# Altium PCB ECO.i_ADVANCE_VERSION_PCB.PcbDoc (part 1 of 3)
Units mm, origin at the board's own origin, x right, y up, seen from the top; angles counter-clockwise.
Board outline 291.08 x 101.6 mm, 4 copper layers (Top Layer, Layer 1, Layer 2, Bottom Layer), stack 1.161 mm thick; 272 components, 228 nets, 849 pads, 240 vias.
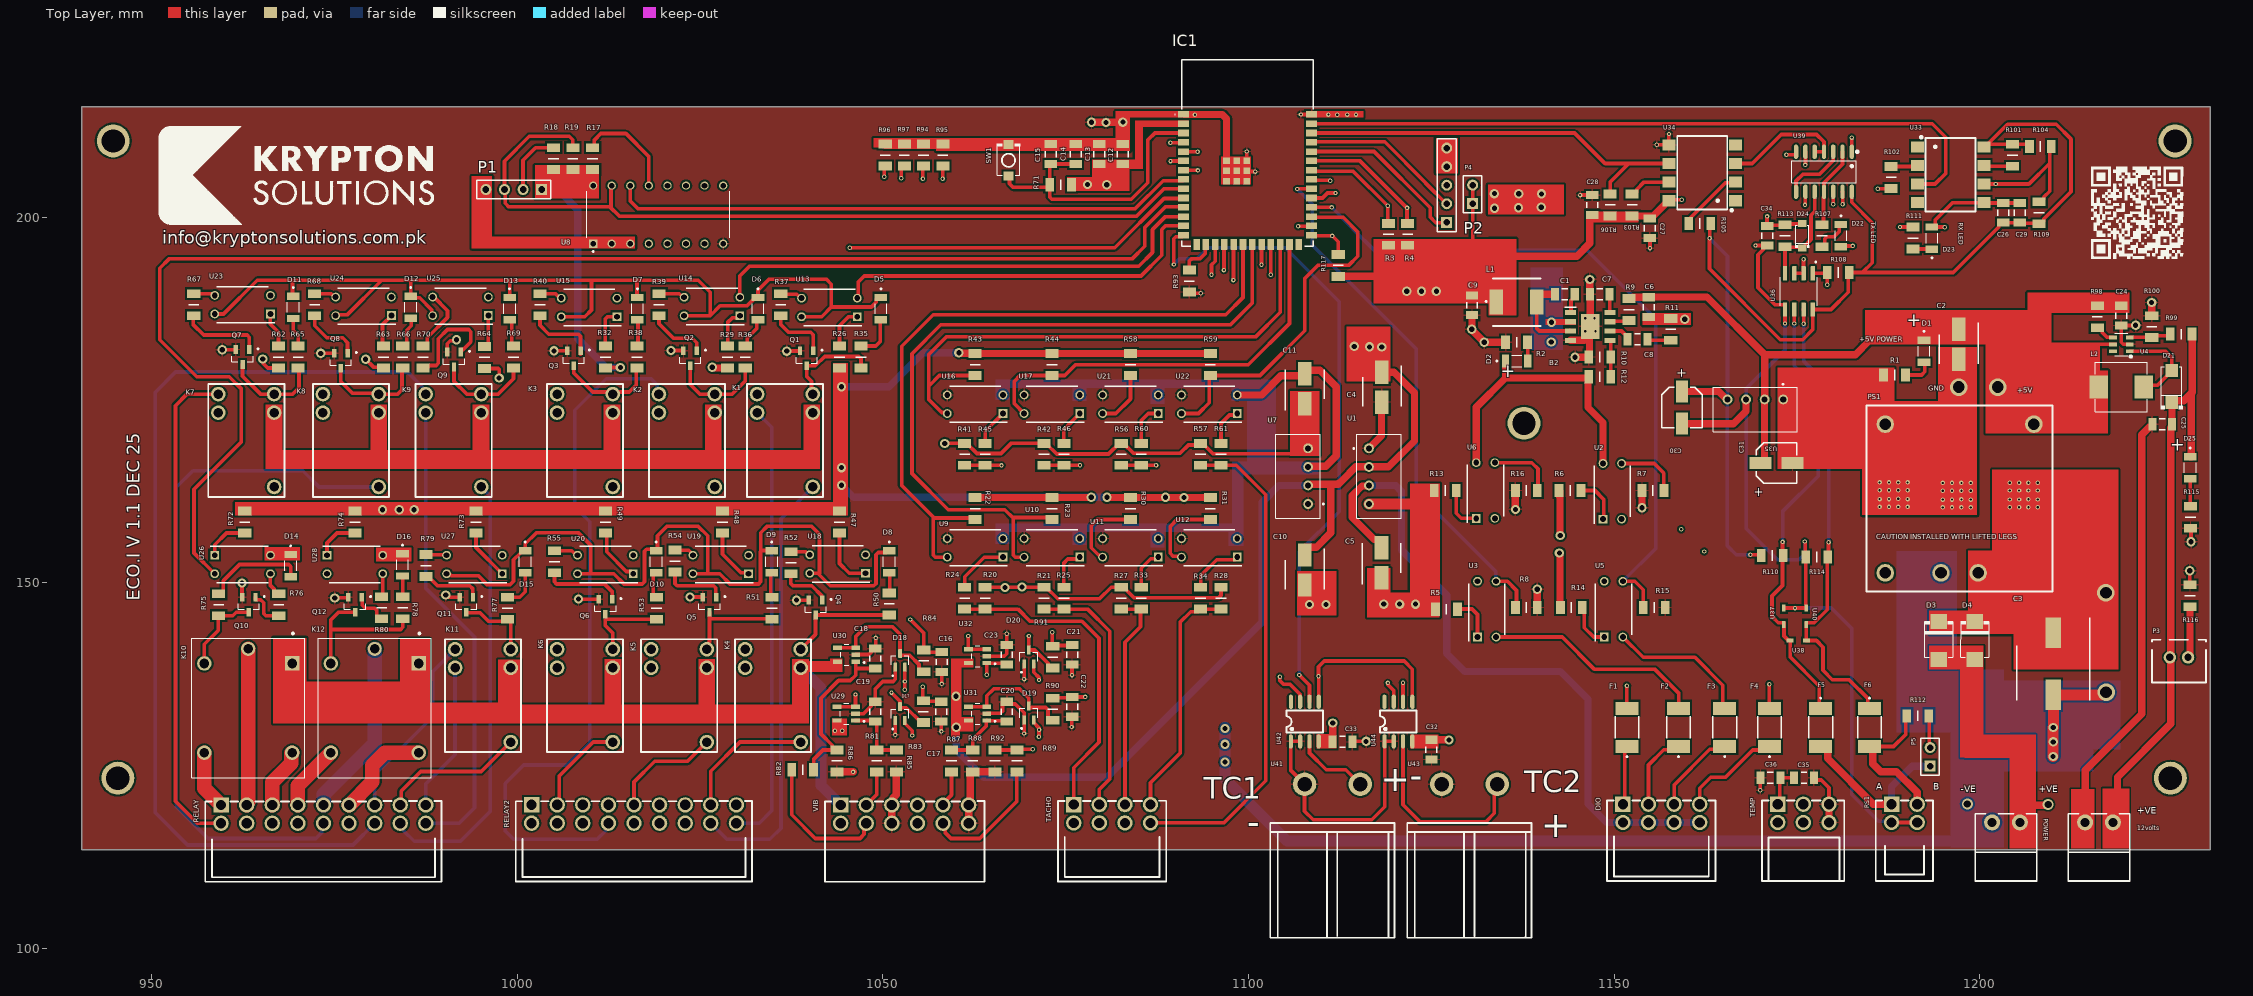
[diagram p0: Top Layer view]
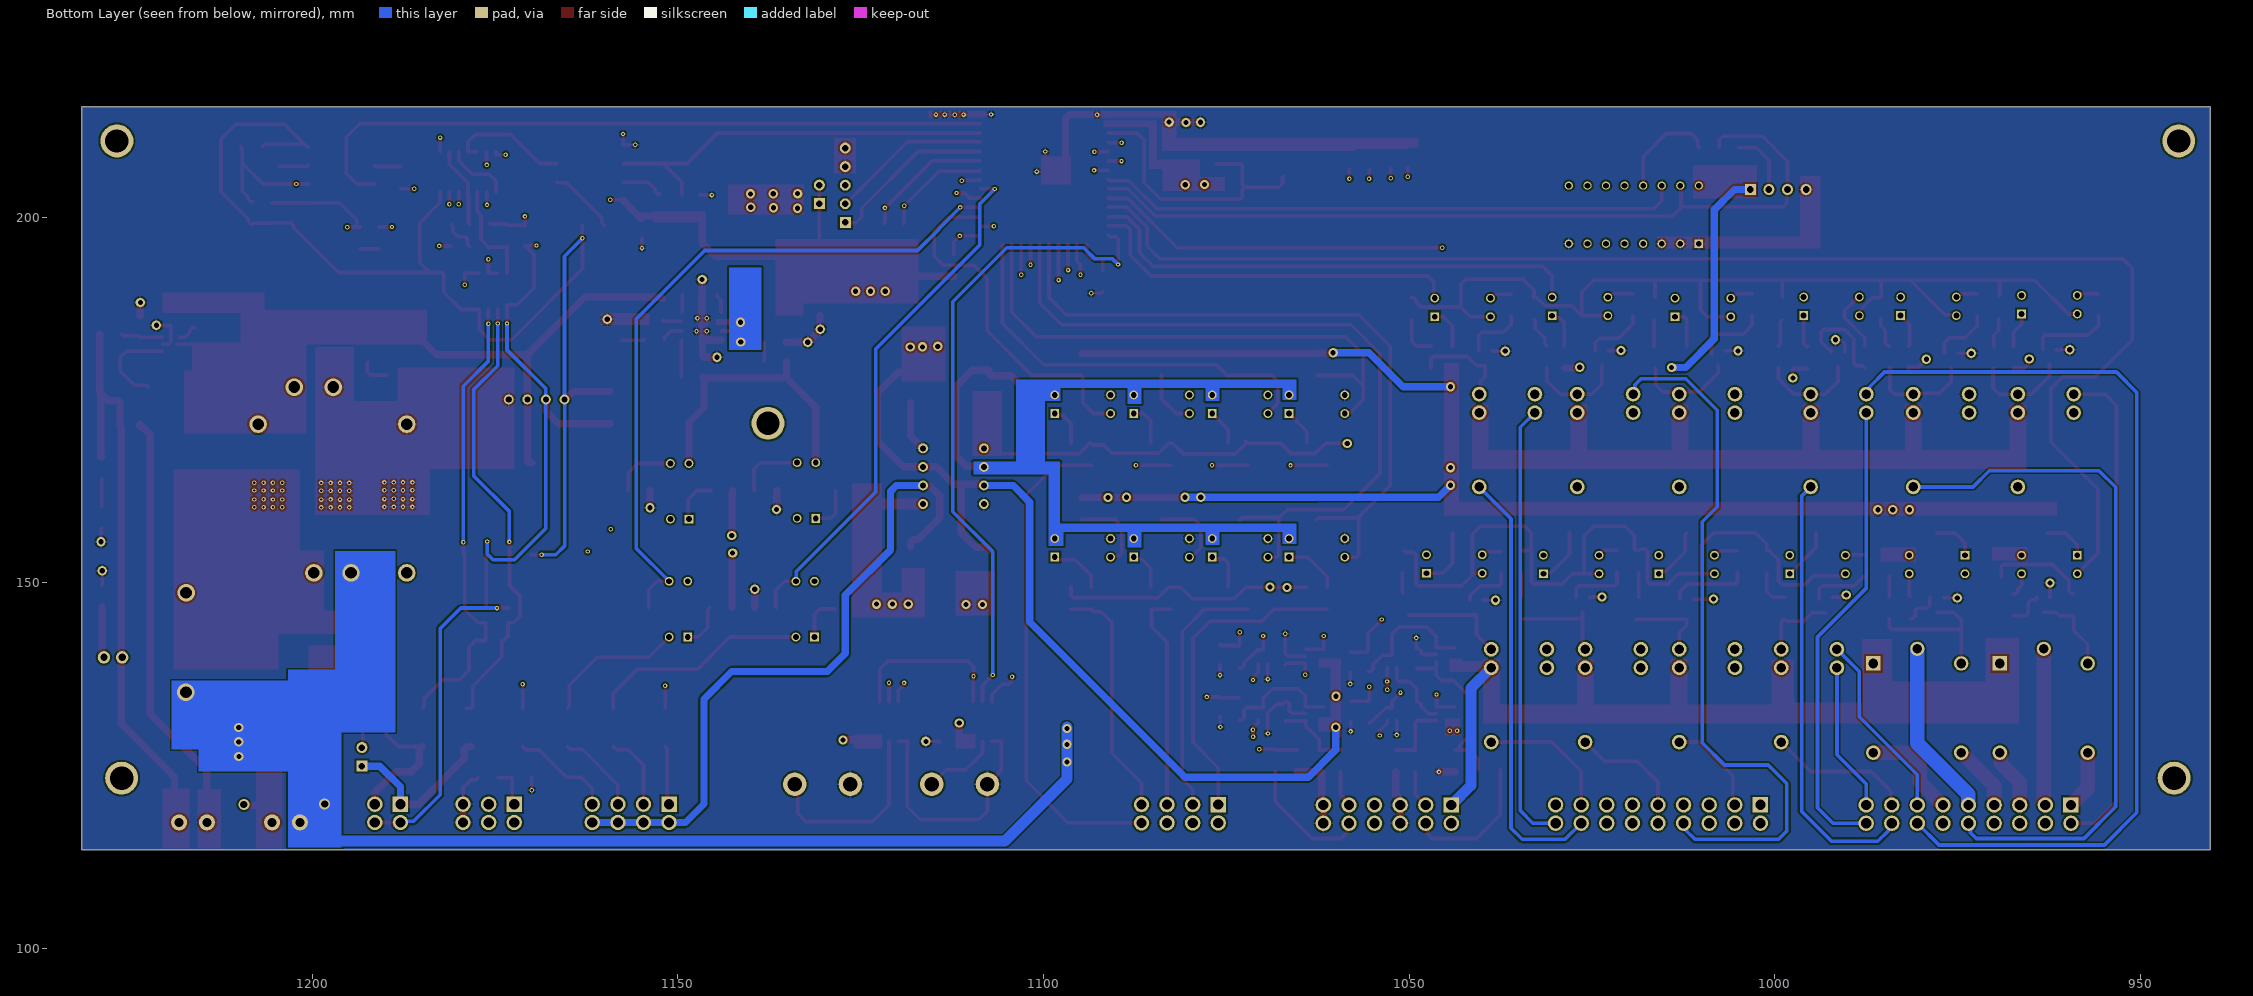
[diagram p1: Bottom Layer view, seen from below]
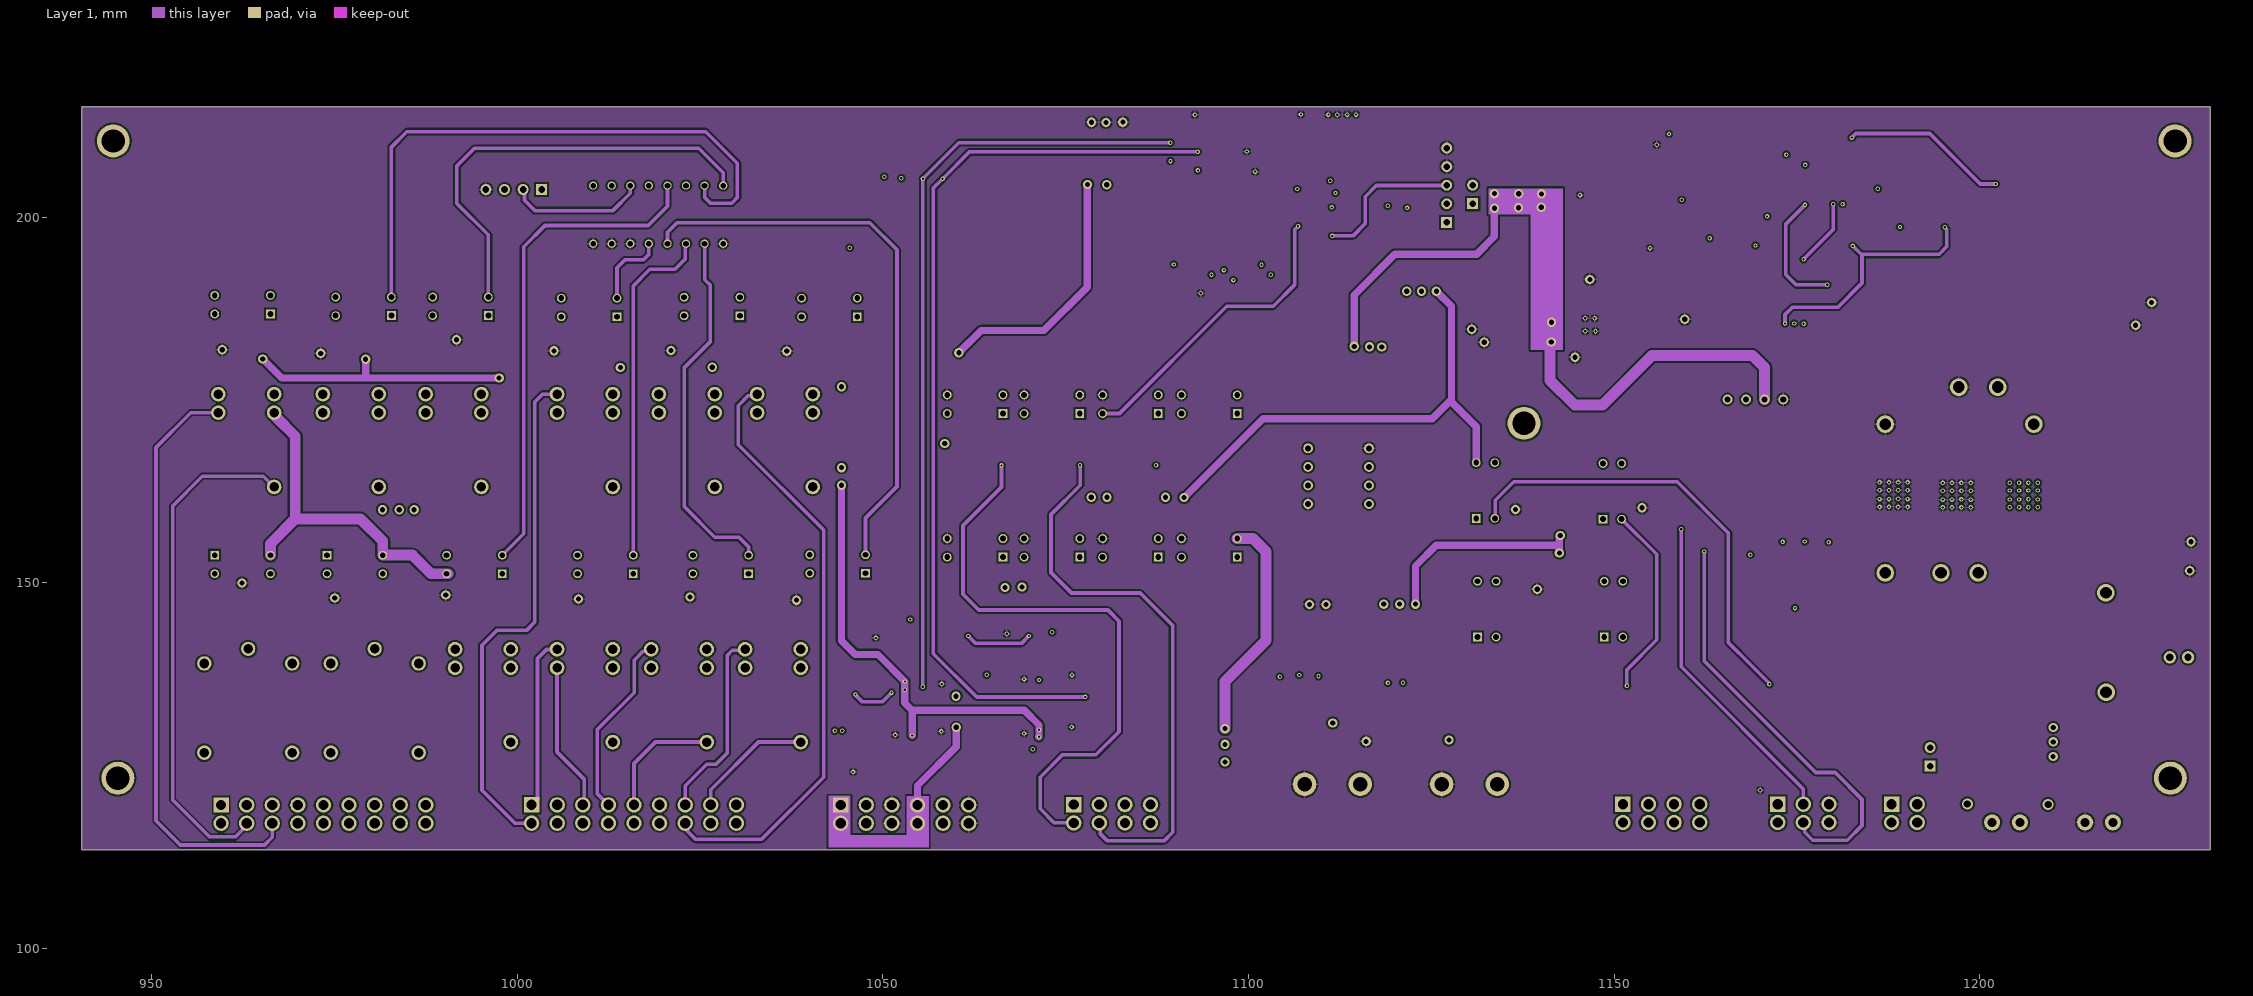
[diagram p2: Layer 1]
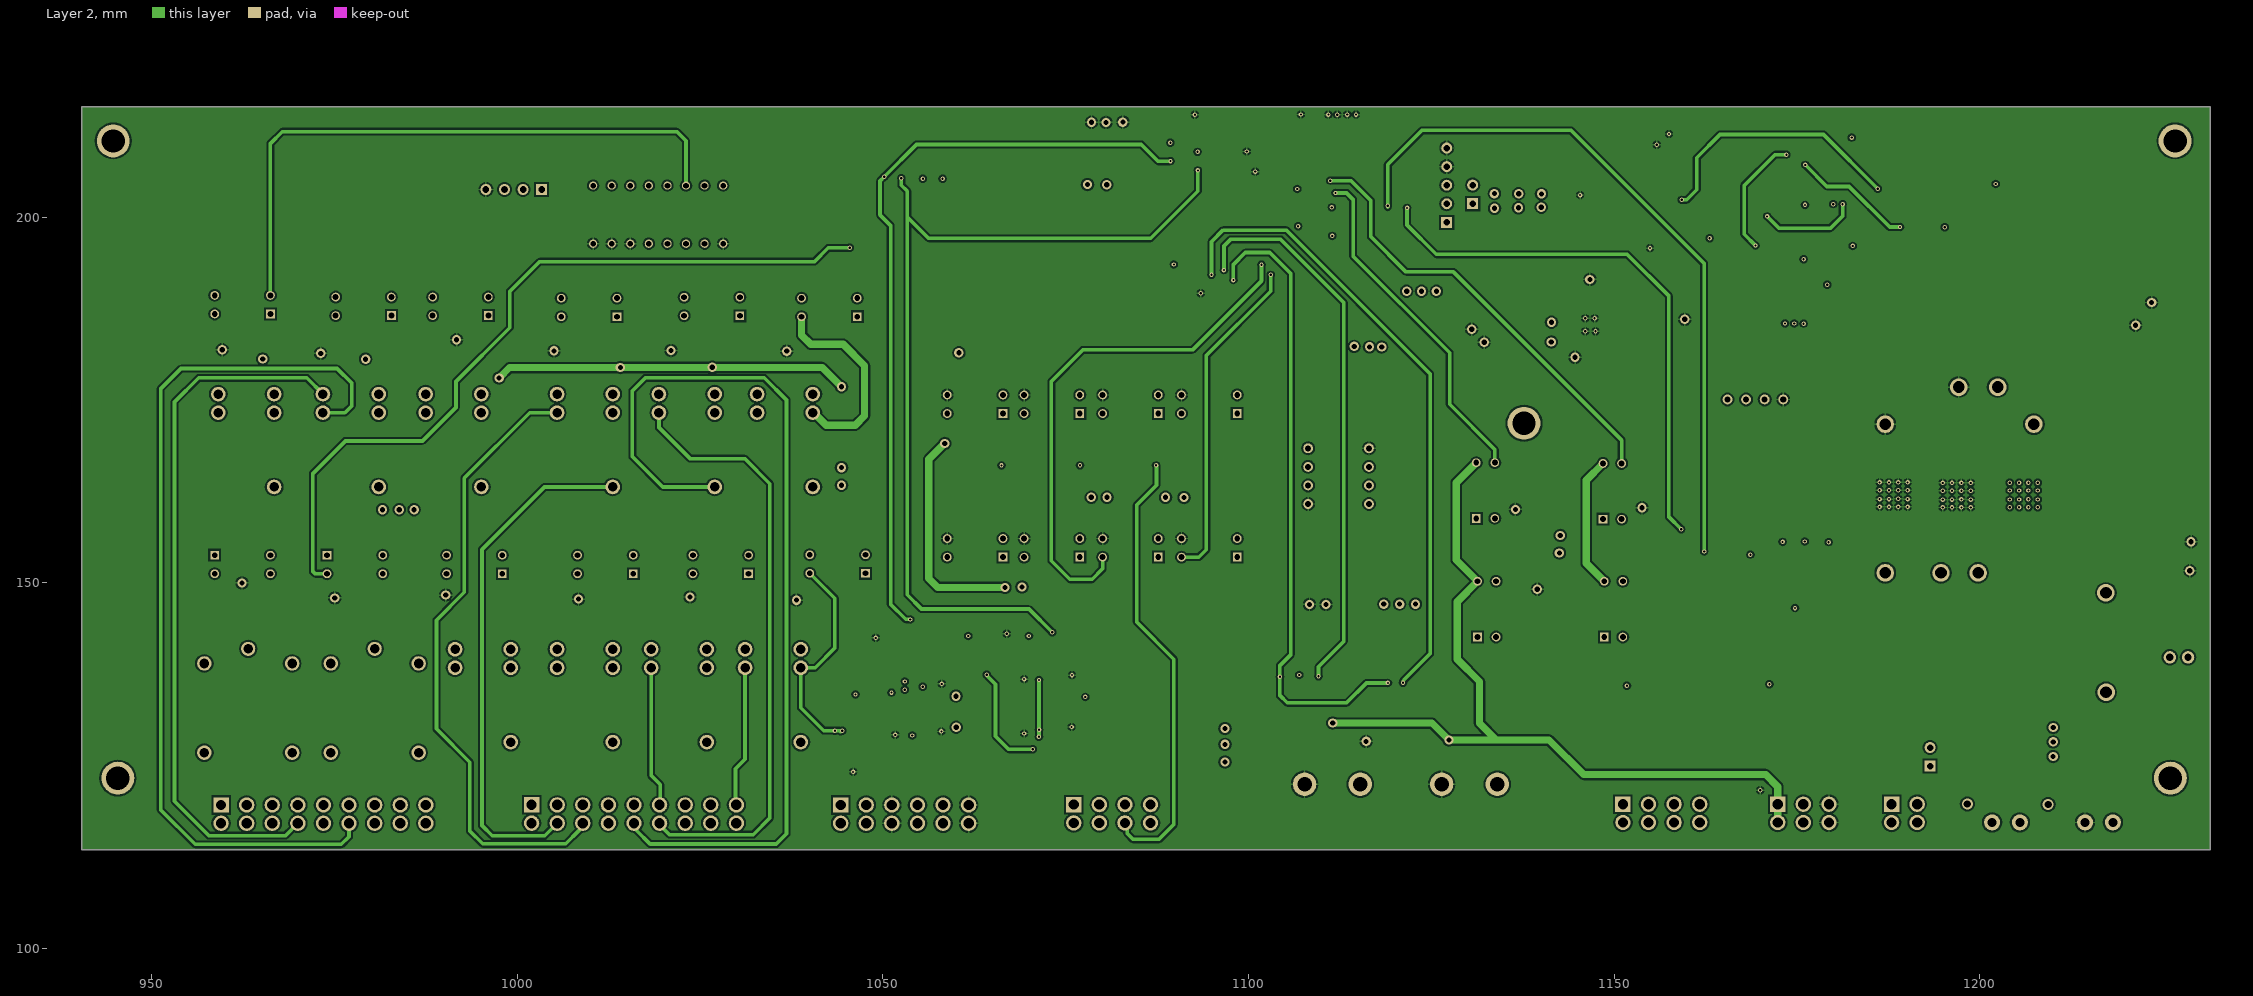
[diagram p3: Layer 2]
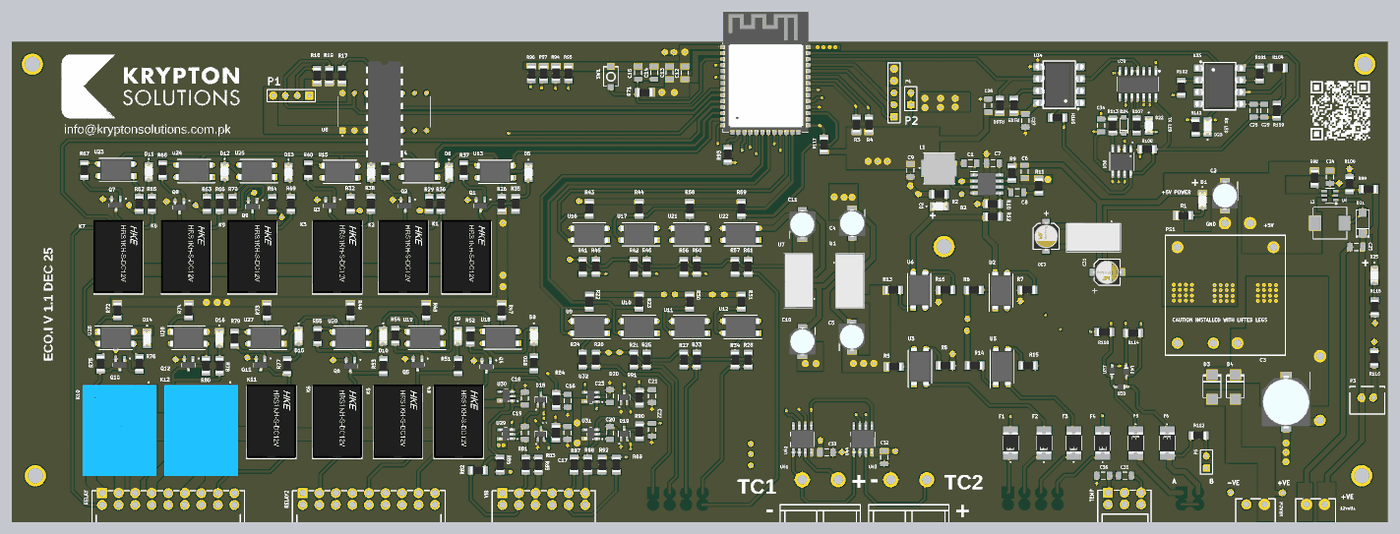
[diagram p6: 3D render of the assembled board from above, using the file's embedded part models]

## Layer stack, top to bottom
Top Solder: solder mask 0.0102, Solder Resist, Dk 3.5
Top Layer: signal copper 0.0356
Dielectric 2: prepreg 0.11, PP-006, Dk 4.1
Layer 1: signal copper 0.035
Dielectric 1: dielectric 0.8, FR-4, Dk 4.8
Layer 2: signal copper 0.035
Dielectric 3: prepreg 0.11, PP-006, Dk 4.1
Bottom Layer: signal copper 0.0356
Bottom Solder: solder mask 0.0102, Solder Resist, Dk 3.5

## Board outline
940.435,113.538 1231.519,113.538 1231.519,215.138 940.435,215.138

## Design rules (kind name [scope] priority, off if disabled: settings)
Clearance [All] p1: gap=0.254 ignorepadtopadclearanceinfootprint=TRUE except(0: Arc-Hole Track-Hole SMDPad-Hole THPad-Hole Via-Hole Fill-Hole Poly-Hole Region-Hole Text-Hole)
HoleSize [All] p1: absolutevalues=TRUE maxlimit=3.5 minlimit=0.025 maxpercent=80.000 minpercent=20.000
MinimumSolderMaskSliver [All] p1: minsoldermaskwidth=0.15
PolygonConnect [All] p1: connectstyle=Relief reliefconductorwidth=0.254 reliefentries=4 polygonreliefangle="90 Angle" airgapwidth=0.254
RoutingVias [All] p1: holewidth=0.72 width=1.27 viastyle="Through Hole" minholewidth=0.29 minwidth=0.5 maxholewidth=3.6 maxwidth=1.27
SilkToSolderMaskClearance [IsPad] p1: minsilkscreentomaskgap=0.01 clearancetoexposedcopper=TRUE
SolderMaskExpansion [All] p1: expansion=0.102 istentingtop=FALSE
SupplyNets "Schematic Supply Nets_10" [InNet('GND')] p1: voltage=0.000
SupplyNets "Schematic Supply Nets_9" [InNet('DGND')] p2: voltage=0.000
SupplyNets "Schematic Supply Nets_8" [InNet('+5V')] p3: voltage=0.000
SupplyNets "Schematic Supply Nets_7" [InNet('+48V')] p4: voltage=0.000
SupplyNets "Schematic Supply Nets_6" [InNet('+5_RS')] p5: voltage=0.000
SupplyNets "Schematic Supply Nets_5" [InNet('AGND')] p6: voltage=0.000
SupplyNets "Schematic Supply Nets_4" [InNet('FGND')] p7: voltage=0.000
SupplyNets "Schematic Supply Nets_3" [InNet('+5V_DIO')] p8: voltage=0.000
SupplyNets "Schematic Supply Nets_2" [InNet('+12')] p9: voltage=0.000
SupplyNets "Schematic Supply Nets_1" [InNet('+5V_FAN')] p10: voltage=0.000
SupplyNets "Schematic Supply Nets" [InNet('+3.3V')] p11: voltage=0.000
Width [All] p1: maxlimit=2 minlimit=0.254 preferedwidth=0.5 midlayer1_maxwidth=1.5 midlayer2_maxwidth=1.5 minimp=50.000000 maximp=50.000000 favimp=50.000000
27 further rules are at their usual default settings.

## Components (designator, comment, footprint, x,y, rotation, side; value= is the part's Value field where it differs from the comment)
12volts "DB2ERC-3.81-2P-BK" CONN-TH_2P-P3.81_DB2ERC-3.81-2P-BK 1216.291,117.247 r0 top
B2 "MP1484EN-LF-Z" SOIC127P600X170-9N 1146.73,185.079 r0 top
C1 "10nF" C1206 1143.252,189.465 r180 top
C2 "10uF" CAP-SMD_BD4.0-L4.3-W4.3-FD 1197.102,182.626 r270 top
C3 "47uF" CAPAE1000X1130N 1210.056,138.938 r270 top
C4 "10uF" CAP-SMD_BD4.0-L4.3-W4.3-FD 1118.235,176.784 r270 top
C5 "10uF" CAP-SMD_BD4.0-L4.3-W4.3-FD 1118.181,152.745 r90 top
C6 "4.7uF" C1206 1154.714,187.716 r270 top
C7 "100nF" C1206 1148.024,189.465 r180 top
C8 "6.8nF" C1206 1153.18,183.304 r0 top
C9 "10uF" C1206 1130.554,187.96 r90 top
C10 "10uF" CAP-SMD_BD4.0-L4.3-W4.3-FD 1107.694,151.765 r270 top
C11 "10uF" CAP-SMD_BD4.0-L4.3-W4.3-FD 1107.694,176.53 r90 top
C12 "22uF" C1206 1082.819,208.641 r90 top
C13 "100nF" C1206 1079.58,208.641 r90 top
C14 "100nF" C1206 1076.342,208.641 r90 top
C15 "100nF" C1206 1072.933,208.641 r90 top
C16 "100nF" C1206 1058.051,139.194 r270 top
C17 "100nF" C1206 1057.985,132.405 r270 top
C18 "100nF" C1206 1048.975,139.67 r90 top
C19 "100nF" C1206 1048.975,132.405 r90 top
C20 "100nF" C1206 1066.953,132.405 r90 top
C21 "100nF" C1206 1075.864,140.178 r270 top
C22 "100nF" C1206 1075.864,133.055 r270 top
C23 "100nF" C1206 1066.953,140.178 r90 top
C24 "22uF" C1206 1219.338,186.555 r270 top
C25 "22uF" C1206 1224.935,171.724 r180 top
C26 "100nF" C1206 1203.198,200.613 r90 top
C27 "100nF" C1206 1154.884,198.504 r270 top
C28 "100nF" C1206 1147.017,201.684 r90 top
C29 "100nF" C1206 1205.452,200.613 r90 top
C30 "10uF" WCAP-ASLI_D5H5.5 1159.277,173.982 r90 top
C31 "10uF" WCAP-ASLI_D5H5.5 1172.182,166.389 r180 top
C32 "100nF" C1206 1125.014,127.21 r90 top
C33 "100nF" C1206 1112.837,128.26 r180 top
C34 "100pF" C1206 1170.924,197.485 r90 top
C35 "100nF" C1206 1175.958,123.344 r0 top
C36 "100nF" C1206 1171.361,123.344 r180 top
D1 "LHN974_RED_LED_1206" LEDC3216X120N 1192.367,181.702 r270 top
D2 "LHN974_RED_LED_1206" LEDC3216X120N 1136.651,180.349 r0 top
D3 "RS3MB" diode_in 1189.94,140.529 r270 top
D4 "RS3MB" diode_in 1194.87,140.529 r270 top
D5 "LHN974_RED_LED_1206" LEDC3216X120N 1049.724,187.523 r270 top
D6 "LHN974_RED_LED_1206" LEDC3216X120N 1032.925,187.523 r270 top
D7 "LHN974_RED_LED_1206" LEDC3216X120N 1016.426,187.523 r270 top
D8 "LHN974_RED_LED_1206" LEDC3216X120N 1050.878,152.908 r270 top
D9 "LHN974_RED_LED_1206" LEDC3216X120N 1034.796,152.908 r270 top
D10 "LHN974_RED_LED_1206" LEDC3216X120N 1018.994,152.908 r270 top
D11 "LHN974_RED_LED_1206" LEDC3216X120N 969.377,187.673 r270 top
D12 "LHN974_RED_LED_1206" LEDC3216X120N 985.435,187.694 r270 top
D13 "LHN974_RED_LED_1206" LEDC3216X120N 998.962,187.523 r270 top
D14 "LHN974_RED_LED_1206" LEDC3216X120N 969.025,152.377 r270 top
D15 "LHN974_RED_LED_1206" LEDC3216X120N 1001.084,152.902 r270 top
D16 "LHN974_RED_LED_1206" LEDC3216X120N 984.312,152.462 r270 top
D17 "BAT54SWFILM" "SOT65P210X110-3N (BAT54SWFILM)" 1052.347,132.131 r90 top
D18 "BAT54SWFILM" "SOT65P210X110-3N (BAT54SWFILM)" 1052.347,139.414 r90 top
D19 "BAT54SWFILM" "SOT65P210X110-3N (BAT54SWFILM)" 1069.961,132.207 r90 top
D20 "BAT54SWFILM" "SOT65P210X110-3N (BAT54SWFILM)" 1069.961,139.89 r90 top
D21 "SS36" SMA_L4.4-W2.6-LS5.0-RD 1226.238,176.85 r90 top
D22 "LHN974_RED_LED_1206" LEDC3216X120N 1180.996,197.506 r270 top
D23 "LHN974_RED_LED_1206" LEDC3216X120N 1193.439,197.16 r90 top
D24 "1N4148W" SOD-123_L2.8-W1.8-LS3.7-RD-1 1175.725,197.485 r90 top
D25 "LHN974_RED_LED_1206" LEDC3216X120N 1228.762,165.742 r270 top
DIO "KF2EDGSR-3.5-2*4P" CONN-TH_8P-P3.50_KEFA_KF2EDGSR-3.5-2X4P 1154.571,103.659 r0 top
F1 "1812L200THPR" 1812L010DR 1151.737,130.243 r90 top
F2 "1812L200THPR" 1812L010DR 1158.806,130.243 r90 top
F3 "1812L200THPR" 1812L010DR 1165.112,130.243 r90 top
F4 "1812L200THPR" 1812L010DR 1171.22,130.243 r90 top
F5 "1812L200THPR" 1812L010DR 1178.237,130.243 r270 top
F6 "1812L200THPR" 1812L010DR 1184.89,130.243 r270 top
IC1 "ESP32-S3-WROOM-1-N16" ESP32S3WROOM1N16 1099.881,208.807 r0 top
K1 "HRS1KH-S-DC5V" RELAY-TH_HRS1KH-S-DCXXX 1041.808,161.6 r90 top
K2 "HRS1KH-S-DC5V" RELAY-TH_HRS1KH-S-DCXXX 1028.395,161.6 r90 top
K3 "HRS1KH-S-DC5V" RELAY-TH_HRS1KH-S-DCXXX 1014.454,161.6 r90 top
K4 "HRS1KH-S-DC5V" RELAY-TH_HRS1KH-S-DCXXX 1040.168,126.717 r90 top
K5 "HRS1KH-S-DC5V" RELAY-TH_HRS1KH-S-DCXXX 1027.326,126.717 r90 top
K6 "HRS1KH-S-DC5V" RELAY-TH_HRS1KH-S-DCXXX 1014.454,126.717 r90 top
K7 "HRS1KH-S-DC5V" RELAY-TH_HRS1KH-S-DCXXX 968.144,161.6 r90 top
K8 "HRS1KH-S-DC5V" RELAY-TH_HRS1KH-S-DCXXX 982.45,161.6 r90 top
K9 "HRS1KH-S-DC5V" RELAY-TH_HRS1KH-S-DCXXX 996.487,161.6 r90 top
K10 "SRD-05VDC-SL-C" RELAY_SRD-05VDC-SL-C 963.212,132.891 r270 top
K11 "HRS1KH-S-DC5V" RELAY-TH_HRS1KH-S-DCXXX 1000.51,126.717 r90 top
K12 "SRD-05VDC-SL-C" RELAY_SRD-05VDC-SL-C 980.51,132.891 r270 top
L1 "SRP6540-100M" SRP6540 1136.651,188.393 r0 top
L2 "22uH" IND-SMD_L7.3-W6.6_MHCI06030 1219.338,176.811 r180 top
P1 "OLED" HDR1X4 1003.336,203.802 r180 top
P2 "PROGRAMMING" HDR1X5 1126.972,209.468 r270 top
P3 "B2B-XH-A(LF)(SN)" CONN-TH_B2B-XH-A-LF-SN 1227.221,139.827 r180 top
P4 "Header 2" HDR1X2 1130.646,201.86 r90 top
P5 "Header 2" HDR1X2 1193.192,124.951 r90 top
POWER "DB2ERC-3.81-2P-BK" CONN-TH_2P-P3.81_DB2ERC-3.81-2P-BK 1203.571,117.247 r0 top
PS1 "URB4805YMD-10WR3" PS1 1188.587,140.529 r0 top
Q1 "FMMT493" SOT91P240X120-3N 1039.579,180.713 r180 top
Q2 "FMMT493" SOT91P240X120-3N 1023.644,180.713 r180 top
Q3 "FMMT493" SOT91P240X120-3N 1007.745,180.721 r180 top
Q4 "FMMT493" SOT91P240X120-3N 1040.803,146.637 r180 top
Q5 "FMMT493" SOT91P240X120-3N 1026.289,147.02 r180 top
Q6 "FMMT493" SOT91P240X120-3N 1012.056,146.748 r180 top
Q7 "FMMT493" SOT91P240X120-3N 962.438,180.892 r180 top
Q8 "FMMT493" SOT91P240X120-3N 975.877,180.407 r180 top
Q9 "FMMT493" SOT91P240X120-3N 991.351,180.554 r180 top
Q10 "FMMT493" SOT91P240X120-3N 963.292,147.02 r180 top
Q11 "FMMT493" SOT91P240X120-3N 993.034,147.02 r180 top
Q12 "FMMT493" SOT91P240X120-3N 977.823,147.02 r180 top
R1 "330Ω" RESC3216X75N 1188.339,178.435 r180 top
R2 "330Ω" RESC3216X75N 1136.651,182.918 r180 top
R3 "10kΩ" RESC3216X75N 1119.131,197.662 r270 top
R4 "4.7k" RESC3216X75N 1121.753,197.662 r270 top
R5 "330Ω" RESC3216X75N 1127.059,146.414 r180 top
R6 "330Ω" RESC3216X75N 1143.97,162.638 r180 top
R7 "10kΩ" RESC3216X75N 1155.293,162.638 r0 top
R8 "4.7k" RESC3216X75N 1137.99,146.643 r180 top
R9 "100kΩ" RESC3216X75N 1152.022,187.391 r270 top
R10 "10kΩ" RESC3216X75N 1148.024,180.888 r0 top
R11 "6.8k" RESC3216X75N 1157.737,184.679 r270 top
R12 "26.1kΩ" RESC3216X75N 1148.024,178.192 r180 top value=26.1k
R13 "330Ω" RESC3216X75N 1126.886,162.638 r180 top
R14 "330Ω" RESC3216X75N 1144.142,146.643 r180 top
R15 "10kΩ" RESC3216X75N 1155.466,146.643 r180 top
R16 "4.7k" RESC3216X75N 1137.99,162.638 r0 top
R17 "10kΩ" RESC3216X75N 1010.301,208.02 r90 top
R18 "10kΩ" RESC3216X75N 1004.97,208.02 r270 top
R19 "10kΩ" RESC3216X75N 1007.607,208.02 r270 top
R20 "10kΩ" RESC3216X75N 1063.984,147.923 r270 top
R21 "10kΩ" RESC3216X75N 1072.016,147.923 r270 top
R22 "10kΩ" RESC3216X75N 1062.611,160.178 r270 top
R23 "10kΩ" RESC3216X75N 1073.117,160.178 r270 top
R24 "330Ω" RESC3216X75N 1061.175,147.923 r270 top
R25 "330Ω" RESC3216X75N 1074.752,147.923 r270 top
R26 "330Ω" RESC3216X75N 1044.069,180.892 r270 top
R27 "10kΩ" RESC3216X75N 1082.601,147.923 r270 top
R28 "10kΩ" RESC3216X75N 1096.226,147.923 r270 top
R29 "330Ω" RESC3216X75N 1028.762,180.892 r270 top
R30 "10kΩ" RESC3216X75N 1083.852,160.178 r270 top
R31 "10kΩ" RESC3216X75N 1094.776,160.178 r270 top
R32 "330Ω" RESC3216X75N 1012.056,180.892 r270 top
R33 "330Ω" RESC3216X75N 1085.337,147.923 r270 top
R34 "330Ω" RESC3216X75N 1093.429,147.923 r270 top
R35 "1kΩ" RESC3216X75N 1047.001,180.892 r90 top
R36 "1kΩ" RESC3216X75N 1031.175,180.892 r90 top
R37 "1kΩ" RESC3216X75N 1036.033,188.048 r270 top
R38 "1kΩ" RESC3216X75N 1016.391,180.892 r90 top
R39 "1kΩ" RESC3216X75N 1019.394,188.048 r270 top
R40 "1kΩ" RESC3216X75N 1003.115,188.031 r270 top
R41 "10kΩ" RESC3216X75N 1061.175,167.581 r270 top
R42 "10kΩ" RESC3216X75N 1072.016,167.581 r270 top
R43 "10kΩ" RESC3216X75N 1062.611,179.863 r270 top
R44 "10kΩ" RESC3216X75N 1073.117,179.863 r270 top
R45 "330Ω" RESC3216X75N 1063.984,167.581 r270 top
R46 "330Ω" RESC3216X75N 1074.752,167.581 r270 top
R47 "330Ω" RESC3216X75N 1044.069,158.331 r90 top
R48 "330Ω" RESC3216X75N 1028.067,158.331 r90 top
R49 "330Ω" RESC3216X75N 1012.056,158.331 r90 top
R50 "1kΩ" RESC3216X75N 1050.878,147.122 r90 top
R51 "1kΩ" RESC3216X75N 1034.831,146.535 r90 top
R52 "1kΩ" RESC3216X75N 1037.422,152.767 r270 top
R53 "1kΩ" RESC3216X75N 1019.029,146.541 r90 top
R54 "1kΩ" RESC3216X75N 1021.566,152.987 r270 top
R55 "1kΩ" RESC3216X75N 1005.088,152.902 r270 top
R56 "10kΩ" RESC3216X75N 1082.601,167.581 r270 top
R57 "10kΩ" RESC3216X75N 1093.429,167.581 r270 top
R58 "10kΩ" RESC3216X75N 1083.852,179.863 r270 top
R59 "10kΩ" RESC3216X75N 1094.776,179.863 r270 top
R60 "330Ω" RESC3216X75N 1085.337,167.581 r270 top
R61 "330Ω" RESC3216X75N 1096.226,167.581 r270 top
R62 "330Ω" RESC3216X75N 967.361,180.892 r270 top
R63 "330Ω" RESC3216X75N 981.709,180.892 r270 top
R64 "330Ω" RESC3216X75N 995.521,180.842 r270 top
R65 "1kΩ" RESC3216X75N 970.037,180.892 r90 top
R66 "1kΩ" RESC3216X75N 984.354,180.892 r90 top
R67 "1kΩ" RESC3216X75N 955.757,188.048 r270 top
R68 "1kΩ" RESC3216X75N 972.297,188.048 r270 top
R69 "1kΩ" RESC3216X75N 999.488,180.892 r90 top
R70 "1kΩ" RESC3216X75N 987.121,180.892 r270 top
R71 "10kΩ" RESC3216X75N 1074.308,204.461 r180 top
R72 "330Ω" RESC3216X75N 962.742,158.331 r90 top
R73 "330Ω" RESC3216X75N 994.363,158.331 r90 top
R74 "330Ω" RESC3216X75N 977.823,158.331 r90 top
R75 "1kΩ" RESC3216X75N 959.168,147.02 r90 top
R76 "1kΩ" RESC3216X75N 967.388,147.02 r270 top
R77 "1kΩ" RESC3216X75N 998.665,146.535 r90 top
R78 "1kΩ" RESC3216X75N 984.347,146.614 r90 top
R79 "1kΩ" RESC3216X75N 987.528,152.377 r270 top
R80 "1kΩ" RESC3216X75N 981.459,146.614 r270 top
R81 "47kΩ" RESC3216X75N 1049.15,125.663 r270 top
R82 "47kΩ" RESC3216X75N 1039.023,124.463 r0 top
R83 "470Ω" RESC3216X75N 1055.531,132.405 r90 top
R84 "470Ω" RESC3216X75N 1055.592,139.345 r90 top
R85 "100kΩ" RESC3216X75N 1051.844,125.663 r90 top
R86 "100kΩ" RESC3216X75N 1043.709,125.663 r90 top
R87 "47kΩ" RESC3216X75N 1059.39,125.663 r90 top
R88 "100kΩ" RESC3216X75N 1062.281,125.663 r90 top
R89 "47kΩ" RESC3216X75N 1068.322,125.663 r90 top
R90 "470Ω" RESC3216X75N 1073.217,132.73 r90 top
R91 "470Ω" RESC3216X75N 1073.217,139.853 r90 top
R92 "100kΩ" RESC3216X75N 1065.319,125.663 r90 top
R93 "10kΩ" RESC3216X75N 1091.909,191.28 r270 top
R94 "10kΩ" RESC3216X75N 1055.538,208.518 r270 top
R95 "10kΩ" RESC3216X75N 1058.202,208.518 r270 top
R96 "10kΩ" RESC3216X75N 1050.33,208.518 r270 top
R97 "10kΩ" RESC3216X75N 1052.934,208.518 r270 top
R98 "10kΩ" RESC3216X75N 1216.069,186.404 r90 top
R99 "62kΩ" RESC3216X75N 1227.527,184.019 r0 top
R100 "3.3kΩ" RESC3216X75N 1223.497,185.049 r270 top
R101 "10kΩ" RESC3216X75N 1204.472,208.477 r90 top
R102 "470Ω" RESC3216X75N 1187.872,205.447 r90 top
R103 "10kΩ" RESC3216X75N 1152.455,201.684 r270 top
R104 "20kΩ" RESC3216X75N 1208.276,209.677 r180 top
R105 "470Ω" RESC3216X75N 1161.693,199.136 r180 top
R106 "10kΩ" RESC3216X75N 1149.447,201.684 r270 top
R107 "2.4kΩ" RESC3216X75N 1178.427,197.485 r270 top
R108 "4.7k" RESC3216X75N 1180.636,192.442 r180 top
R109 "4.7k" RESC3216X75N 1208.099,200.613 r90 top
R110 "4.7k" RESC3216X75N 1171.602,153.744 r0 top
R111 "2.4kΩ" RESC3216X75N 1190.869,197.16 r90 top
R112 "120Ω" RESC3216X75N 1191.514,131.826 r0 top
R113 "56kΩ" RESC3216X75N 1173.353,197.485 r90 top
R114 "4.7k" RESC3216X75N 1177.691,153.543 r180 top
R115 "1kΩ" RESC3216X75N 1228.797,158.99 r90 top
R116 "1kΩ" RESC3216X75N 1228.727,148.247 r90 top
R117 "10kΩ" RESC3216X75N 1112.266,193.421 r270 top
RELAY "KF2EDGSR-3.5-2*9P" CONN-TH_18P-P3.50_KEFA_KF2EDGSR-3.5-2X9P 972.404,111.674 r0 top
RELAY2 "KF2EDGSR-3.5-2*9P" CONN-TH_18P-P3.50_KEFA_KF2EDGSR-3.5-2X9P 1014.866,111.694 r0 top
RS1 "KF2EDGSR-3.5-2*2P" CONN-TH_4P-P3.50_KEFA_KF2EDGSR-3.5-2X2P 1189.528,107.85 r0 top
SW1 "TS-1088-AR02016" SW-SMD_L3.9-W3.0-P4.45 1070.195,205.252 r90 top
TACHO "KF2EDGSR-3.5-2*4P" CONN-TH_8P-P3.50_KEFA_KF2EDGSR-3.5-2X4P 1079.474,103.599 r0 top
TEMP "KF2EDGSR-3.5-2*3P" CONN-TH_6P-P3.50_KEFA_KF2EDGSR-3.5-2X3P 1175.866,118.497 r0 top
U1 "B0505S-1WR3" TME0512S 1114.788,164.603 r270 top
U2 "PC817C" DIP762W60P254L460H455Q4N 1149.741,162.532 r90 top
U3 "PC817C" DIP762W60P254L460H455Q4N 1132.581,146.414 r90 top
U4 "MT3608" SOT-23-6_L2.9-W1.6-P0.95-LS2.8-BL 1219.338,182.626 r90 top
U5 "PC817C" DIP762W60P254L460H455Q4N 1149.914,146.414 r90 top
U6 "PC817C" DIP762W60P254L460H455Q4N 1132.408,162.638 r90 top
U7 "B0505S-1WR3" TME0512S 1109.824,164.603 r90 top
U8 "PCF8574P,112" DIP794W45P254L1969H508Q16 1019.267,200.362 r90 top
U9 "PC817C" DIP762W60P254L460H455Q4N 1062.611,154.799 r180 top
U10 "PC817C" DIP762W60P254L460H455Q4N 1073.117,154.799 r180 top
U11 "PC817C" DIP762W60P254L460H455Q4N 1083.852,154.799 r180 top
U12 "PC817C" DIP762W60P254L460H455Q4N 1094.641,154.799 r180 top
U13 "PC817C" DIP762W60P254L460H455Q4N 1042.689,187.673 r180 top
U14 "PC817C" DIP762W60P254L460H455Q4N 1026.629,187.803 r180 top
U15 "PC817C" DIP762W60P254L460H455Q4N 1009.828,187.673 r180 top
U16 "PC817C" DIP762W60P254L460H455Q4N 1062.611,174.437 r180 top
U17 "PC817C" DIP762W60P254L460H455Q4N 1073.117,174.437 r180 top
U18 "PC817C" DIP762W60P254L460H455Q4N 1043.815,152.588 r180 top
U19 "PC817C" DIP762W60P254L460H455Q4N 1027.83,152.527 r180 top
U20 "PC817C" DIP762W60P254L460H455Q4N 1012.056,152.527 r180 top
U21 "PC817C" DIP762W60P254L460H455Q4N 1083.852,174.437 r180 top
U22 "PC817C" DIP762W60P254L460H455Q4N 1094.641,174.437 r180 top
U23 "PC817C" DIP762W60P254L460H455Q4N 962.438,188.048 r180 top
U24 "PC817C" DIP762W60P254L460H455Q4N 978.98,187.823 r180 top
U25 "PC817C" DIP762W60P254L460H455Q4N 992.236,187.823 r180 top
U26 "PC817C" DIP762W60P254L460H455Q4N 962.438,152.527 r0 top
U27 "PC817C" DIP762W60P254L460H455Q4N 994.149,152.527 r180 top
U28 "PC817C" DIP762W60P254L460H455Q4N 977.799,152.527 r0 top
U29 "LM321" SOT95P280X145-5N 1044.991,132.131 r180 top
U30 "LM321" SOT95P280X145-5N 1045.029,140.178 r180 top
U31 "LM321" SOT95P280X145-5N 1062.946,132.131 r180 top
U32 "LM321" SOT95P280X145-5N 1062.946,139.995 r180 top
U33 "6N137S-TA1-L" 6N137S-TA1-L 1195.899,206.454 r270 top
U34 "6N137S-TA1-L" 6N137S-TA1-L 1162.146,205.447 r90 top
U35 "B0505S-1WR3" TME0512S 1169.307,176.768 r180 top
U36 "SN75176BDR" SOIC127P599X175-8N 1175.258,189.865 r270 top
U37 "LKS05D3-B" "TVS DIODE" 1174.456,143.795 r90 top
U38 "LKS05D3-B" "TVS DIODE" 1176.828,143.379 r180 top
U39 "CD4069" SOP-14_L8.8-W3.9-P1.27-LS6.0-BL 1178.68,206.231 r180 top
U40 "LKS05D3-B" "TVS DIODE" 1175,147.098 r270 top
U41 "DBT30R-7.62-2P-BK-P" CONN-TH_2P-P7.62_DBT30R-7.62-2P 1111.47,122.476 r0 top
U42 "MAX6675ISA+T" SOIC-8_L5.0-W4.0-P1.27-LS6.0-BL 1107.694,131.042 r0 top
U43 "DBT30R-7.62-2P-BK-P" CONN-TH_2P-P7.62_DBT30R-7.62-2P 1130.209,122.477 r0 top
U44 "MAX6675ISA+T" SOIC-8_L5.0-W4.0-P1.27-LS6.0-BL 1120.49,131.042 r0 top
VIB "KF2EDGSR-3.5-2*6P" CONN-TH_12P-P3.50_KEFA_KF2EDGSR-3.5-2X6P 1052.613,110.665 r0 top

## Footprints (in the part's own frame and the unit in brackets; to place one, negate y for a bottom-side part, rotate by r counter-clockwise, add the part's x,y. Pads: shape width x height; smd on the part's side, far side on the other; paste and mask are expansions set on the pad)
6N137S-TA1-L [mm]
  rect 1.525x1.78 smd: 1(-3.175,-4.418) 2(-0.635,-4.418) 3(1.905,-4.418) 4(4.445,-4.418) 5(4.445,4.672) 6(1.905,4.672) 7(-0.635,4.672) 8(-3.175,4.672)
  silkscreen extent -4.63,-4.06 5.66,3.52, body extent -4.21,-5.08 5.47,5.08, height 4.61
1812L010DR [mm]
  rect 1.78x3.15 smd: 1(-2.615,0) 2(2.615,0)
  silkscreen extent -4.1,-1.62 1.5,1.62, body extent -2.28,-1.63 2.28,1.63, height 0.75
C1206 [mm] "Chip Capacitor, Body 3.2x1.6mm, IPC High Density"
  rect 1.1x1.7 smd: 1(-1.35,0) 2(1.35,0)
  silkscreen extent -0.4,-0.75 0.4,0.75, body extent -1.7,-0.9 1.7,0.9, height 1.3
CAP-SMD_BD4.0-L4.3-W4.3-FD [mm]
  rect 3.2x1.85 smd: 1(-2.05,0) 2(2.05,0)
  silkscreen extent -2.92,-2.65 2.65,2.67, body extent -2.95,-2.75 2.95,2.75, height 5.5
CAPAE1000X1130N [mm]
  rect 4.15x2.1 smd: 1(-4.25,0) 2(4.25,0)
  silkscreen extent -6.32,-5 5,5, body extent -5.6,-5.1 5.6,5.1, height 11.3
CONN-TH_2P-P3.81_DB2ERC-3.81-2P-BK [mm]
  round 2.2 hole 1.27: 1(-1.905,0) 2(1.905,0)
  silkscreen extent -4.21,-8 4.21,1.2
CONN-TH_2P-P7.62_DBT30R-7.62-2P [mm]
  round 3.2 hole 2: 1(-3.81,0) 2(3.81,0)
  silkscreen extent -8.5,-21 8.5,-5.3
CONN-TH_4P-P3.50_KEFA_KF2EDGSR-3.5-2X2P [mm]
  rect 2.1x2.1 hole 1.4 paste-2539.97 mask+0.05: 1(-1.6,11.897)
  round 2.1 hole 1.4 paste-2539.97 mask+0.05: 2(-1.6,9.397) 3(1.9,11.897) 4(1.9,9.397)
  silkscreen extent -3.76,1.4 4.05,12.42
CONN-TH_6P-P3.50_KEFA_KF2EDGSR-3.5-2X3P [mm]
  rect 2.1x2.1 hole 1.4 paste-2539.97 mask+0.05: 1(-3.5,1.25)
  round 2.1 hole 1.4 paste-2539.97 mask+0.05: 2(-3.5,-1.25) 3(0,1.25) 5(3.5,1.25) 6(3.5,-1.25)
  round 2.1 hole 1.4 copper offset 0,0 paste-2539.97 mask+0.05: 4(0,-1.25)
  silkscreen extent -5.66,-9.25 5.6,1.78
CONN-TH_8P-P3.50_KEFA_KF2EDGSR-3.5-2X4P [mm]
  rect 2.1x2.1 hole 1.4 paste-2539.97 mask+0.05: 1(-3.378,16.088)
  round 2.1 hole 1.4 paste-2539.97 mask+0.05: 2(-3.378,13.588) 3(0.122,16.088) 5(3.622,16.088) 6(3.622,13.588) 7(7.122,16.088) 8(7.122,13.588)
  round 2.1 hole 1.4 copper offset 0,0 paste-2539.97 mask+0.05: 4(0.122,13.588)
  silkscreen extent -5.54,5.59 9.27,16.62
CONN-TH_12P-P3.50_KEFA_KF2EDGSR-3.5-2X6P [mm]
  rect 2.1x2.1 hole 1.4 paste-2539.97 mask+0.05: 1(-8.388,8.969)
  round 2.1 hole 1.4 paste-2539.97 mask+0.05: 2(-8.388,6.469) 3(-4.888,8.969) 5(-1.388,8.969) 6(-1.388,6.469) 7(2.112,8.969) 8(2.112,6.469) 9(5.612,8.969) 10(5.612,6.469) 11(9.112,8.969) 12(9.112,6.469)
  round 2.1 hole 1.4 copper offset 0,0 paste-2539.97 mask+0.05: 4(-4.888,6.469)
  silkscreen extent -10.55,-1.53 11.26,9.5
CONN-TH_18P-P3.50_KEFA_KF2EDGSR-3.5-2X9P [mm]
  rect 2.1x2.1 hole 1.4 paste-2539.97 mask+0.05: 1(-12.903,7.96)
  round 2.1 hole 1.4 paste-2539.97 mask+0.05: 2(-12.903,5.46) 3(-9.403,7.96) 5(-5.903,7.96) 6(-5.903,5.46) 7(-2.403,7.96) 8(-2.403,5.46) 9(1.097,7.96) 10(1.097,5.46) 11(4.597,7.96) 12(4.597,5.46) 13(8.097,7.96) 14(8.097,5.46) 15(11.597,7.96) 17(15.097,7.96) 18(15.097,5.46)
  round 2.1 hole 1.4 copper offset 0,0 paste-2539.97 mask+0.05: 4(-9.403,5.46) 16(11.597,5.46)
  silkscreen extent -15.06,-2.54 17.25,8.49
CONN-TH_B2B-XH-A-LF-SN [mm]
  round 1.7 hole 1: 1(1.25,0) 2(-1.25,0)
  silkscreen extent -3.68,-2.41 3.68,3.43
diode_in [mil]
  rect 80.61x88.23 smd: 1(-164.7,175) 2(39.34,175)
  silkscreen extent -168,100 26,250
DIP762W60P254L460H455Q4N [mm]
  rect 1.2x1.2 hole 0.8: 1(-3.81,1.27)
  round 1.2 hole 0.8: 2(-3.81,-1.27) 3(3.81,-1.27) 4(3.81,1.27)
  silkscreen extent -4.41,-2.48 3.5,2.47, body extent -3.96,-2.3 3.96,2.3, height 4.55
DIP794W45P254L1969H508Q16 [mm]
  rect 1.13x1.13 / inner round 1.13 / far side rect 1.13x1.13 hole 0.78: 1(-3.97,8.89)
  round 1.13 hole 0.78: 2(-3.97,6.35) 3(-3.97,3.81) 4(-3.97,1.27) 5(-3.97,-1.27) 6(-3.97,-3.81) 7(-3.97,-6.35) 8(-3.97,-8.89) 9(3.97,-8.89) 10(3.97,-6.35) 11(3.97,-3.81) 12(3.97,-1.27) 13(3.97,1.27) 14(3.97,3.81) 15(3.97,6.35) 16(3.97,8.89)
  silkscreen extent -5.13,-9.78 3.18,9.77, body extent -3.95,-10.67 3.95,10.67, height 5.08
ESP32S3WROOM1N16 [mm]
  rect 1.5x0.9 smd: 1(-8.75,5.26) 2(-8.75,3.99) 3(-8.75,2.72) 4(-8.75,1.45) 5(-8.75,0.18) 6(-8.75,-1.09) 7(-8.75,-2.36) 8(-8.75,-3.63) 9(-8.75,-4.9) 10(-8.75,-6.17) 11(-8.75,-7.44) 12(-8.75,-8.71) 13(-8.75,-9.98) 14(-8.75,-11.25) 27(8.75,-11.25) 28(8.75,-9.98) 29(8.75,-8.71) 30(8.75,-7.44) 31(8.75,-6.17) 32(8.75,-4.9) 33(8.75,-3.63) 34(8.75,-2.36) 35(8.75,-1.09) 36(8.75,0.18) 37(8.75,1.45) 38(8.75,2.72) 39(8.75,3.99) 40(8.75,5.26)
  rect 0.9x1.5 smd: 15(-6.985,-12.5) 16(-5.715,-12.5) 17(-4.445,-12.5) 18(-3.175,-12.5) 19(-1.905,-12.5) 20(-0.635,-12.5) 21(0.635,-12.5) 22(1.905,-12.5) 23(3.175,-12.5) 24(4.445,-12.5) 25(5.715,-12.5) 26(6.985,-12.5)
  rect 0.9x0.9 smd: 41(-1.5,-2.46) 42(-1.5,-1.06) 43(-2.9,-1.06) 44(-2.9,-2.46) 45(-2.9,-3.86) 46(-1.5,-3.86) 47(-0.1,-3.86) 48(-0.1,-2.46) 49(-0.1,-1.06)
  silkscreen extent -10,-12.75 9,12.75, body extent -9,-12.76 9,12.74, height 3.25
HDR1X2 [mm] "Connector; Header; 2 Position"
  rect 1.5x1.5 hole 0.9: 1(0,0)
  round 1.5 hole 0.9: 2(2.54,0)
  silkscreen extent -1.27,-1.27 3.81,1.27
HDR1X4 [mm] "Connector; Header; 4 Position"
  rect 1.5x1.5 hole 0.9: 1(0,0)
  round 1.5 hole 0.9: 2(2.54,0) 3(5.08,0) 4(7.62,0)
  silkscreen extent -1.27,-1.27 8.89,1.27
HDR1X5 [mm] "Connector; Header; 5 Position"
  rect 1.5x1.5 hole 0.9: 1(10.16,0.127)
  round 1.5 hole 0.9: 2(7.62,0.127) 3(5.08,0.127) 4(2.54,0.127) 5(0,0.127)
  silkscreen extent -1.27,-1.14 11.43,1.4
IND-SMD_L7.3-W6.6_MHCI06030 [mm]
  rect 2.524x3.12 smd: 1(-3.078,0) 2(3.078,0)
  silkscreen extent -3.58,-3.38 3.58,3.38
LEDC3216X120N [mm]
  rect 1.01x1.73 smd: NEG(1.51,0) POS(-1.51,0)
  silkscreen extent -2.8,-0.8 0.68,0.8, body extent -1.6,-0.8 1.6,0.8, height 1.2
PS1 [mm]
  round 2.4 hole 1.6 paste-2539.97 mask+0.05: 1(6.096,10.855) 2(11.176,10.855) 3(18.796,31.175) 5(-1.524,31.175) 6(-1.524,10.855)
  silkscreen extent -4.06,8.31 21.34,33.71
RELAY-TH_HRS1KH-S-DCXXX [mm]
  round 2 hole 1.3: 1(1.524,1.397) 2(11.684,1.397) 3(14.224,1.397) 4(14.224,9.017) 5(11.684,9.017)
  silkscreen extent 0.17,-0.02 15.59,10.39, body extent 0.38,-0.04 15.88,10.46, height 11.81
RELAY_SRD-05VDC-SL-C [mm]
  rect 1.98x1.98 / inner round 1.98 / far side rect 1.98x1.98 hole 1.32: A1(-6.1,6)
  round 1.98 hole 1.32: A2(-6.1,-6) NC(6.1,6) NO(6.1,-6)
  round 1.935 hole 1.29: COM(-8.1,0)
  silkscreen extent -10.3,-7.75 9.55,7.75, body extent -9.6,-7.8 9.6,7.8, height 15.8
RESC3216X75N [mm]
  rect 1.2x1.8 smd: 1(-1.5,0) 2(1.5,0)
  silkscreen extent 0,-0.7 0,0.7, body extent -1.6,-0.8 1.6,0.8, height 0.75
SMA_L4.4-W2.6-LS5.0-RD [mm]
  rect 1.8x1.7 smd: 1(-2.193,0) 2(2.193,0)
  silkscreen extent -3.11,-1.48 2.73,1.48
SOD-123_L2.8-W1.8-LS3.7-RD-1 [mm]
  rect 0.95x1.15 smd: 1(-1.692,0) 2(1.692,0)
  silkscreen extent -1.63,-0.94 1.41,0.94
SOIC127P599X175-8N [mm]
  rrect25% 1.97x0.6 smd: 1(-2.47,1.905) 2(-2.47,0.635) 3(-2.47,-0.635) 4(-2.47,-1.905) 5(2.47,-1.905) 6(2.47,-0.635) 7(2.47,0.635) 8(2.47,1.905)
  silkscreen extent -4.14,-2.52 1.95,2.52, body extent -3,-2.45 3,2.45, height 1.75
SOIC127P600X170-9N [mm]
  rect 1.525x0.7 smd: 1(-2.712,1.905) 2(-2.712,0.635) 3(-2.712,-0.635) 4(-2.712,-1.905) 5(2.712,-1.905) 6(2.712,-0.635) 7(2.712,0.635) 8(2.712,1.905)
  rect 2.56x3.45 smd: 9(0,0)
  silkscreen extent -3.48,2.6 -1.95,2.6, body extent -3,-2.45 3,2.45, height 1.7
SOIC-8_L5.0-W4.0-P1.27-LS6.0-BL [mil]
  oval 22.38x76.78 smd: 1(-75,-106.5) 2(-25,-106.5) 3(25,-106.5) 4(75,-106.5) 5(75,106.5) 6(25,106.5) 7(-25,106.5) 8(-75,106.5)
  silkscreen extent -98,-59 98,59, body extent -97,-116 96,120, height 69
SOP-14_L8.8-W3.9-P1.27-LS6.0-BL [mm]
  oval 0.595x1.968 smd: 1(-3.81,-2.734) 2(-2.54,-2.734) 3(-1.27,-2.734) 4(0,-2.734) 5(1.27,-2.734) 6(2.54,-2.734) 7(3.81,-2.734) 8(3.81,2.734) 9(2.54,2.734) 10(1.27,2.734) 11(0,2.734) 12(-1.27,2.734) 13(-2.54,2.734) 14(-3.81,2.734)
  silkscreen extent -4.71,-2.88 4.4,1.52, body extent -4.32,-2.98 4.33,3.04, height 1.75
"SOT65P210X110-3N (BAT54SWFILM)" [mm]
  rrect25% 1.23x0.5 smd: 1(-0.94,0.65) 2(-0.94,-0.65) 3(0.94,0)
  silkscreen extent -2.2,-1.21 0.62,1.21, body extent -1.05,-1 1.05,1, height 1.1
SOT91P240X120-3N [mm]
  rect 0.61x1.18 smd: 1(-0.915,-1.025) 2(0.915,-1.025) 3(0,1.025)
  silkscreen extent -2.21,-1.21 1.45,0.65, body extent -1.45,-0.95 1.45,1.45, height 1.15
SOT95P280X145-5N [mm]
  rrect9% 1.21x0.59 smd: 1(-1.255,0.95) 2(-1.255,0) 3(-1.255,-0.95) 4(1.255,-0.95) 5(1.255,0.95)
  silkscreen extent -2.51,-1.45 0.8,1.45, body extent -1.4,-1.45 1.4,1.45, height 1.45
SOT-23-6_L2.9-W1.6-P0.95-LS2.8-BL [mm]
  rect 0.532x1.072 smd: 1(-0.95,-1.149) 2(0,-1.149) 3(0.95,-1.149) 4(0.95,1.149) 5(0,1.149) 6(-0.95,1.149)
  silkscreen extent -1.82,-1.45 1.54,0.89
SRP6540 [mm]
  rect 1.85x3.4 smd: 1(-2.775,0) 2(2.775,0)
  silkscreen extent -4.23,-3.25 3.25,3.25, body extent -3.59,-3.25 3.59,3.25, height 3.99
SW-SMD_L3.9-W3.0-P4.45 [mm]
  rect 1.23x1.36 smd: 1(0.361,3.014) 2(4.731,3.014)
  silkscreen extent 0.52,1.4 4.8,4.63
TME0512S [mm]
  round 1.349 hole 0.83: 1(-3.81,1.675) 2(-1.27,1.675) 3(1.27,1.675) 4(3.81,1.675)
  silkscreen extent -5.75,-0.5 5.75,6.1, body extent -5.66,-0.12 5.74,5.88, height 9.95
"TVS DIODE" [mm]
  rect 0.985x0.49 smd: 1(0.534,1.245) 2(2.769,1.245)
  body extent 0.41,0.58 2.91,1.86, height 1
WCAP-ASLI_D5H5.5 [mm] "Aluminium Electrolytic V-Chip SMT Capacitors, 5x5.5mm"
  rect 3x1.6 smd: 1(2.2,0) 2(-2.2,0)
  silkscreen extent -2.75,-2.75 2.75,2.75, body extent -3,-2.65 3,2.65, height 5.5

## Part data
12volts POWER: library part DB2ERC-3.81-2P-BK_C5259145, Color=Black, Current Rating=8A, JLCPCB Part Class="Extended Part", LCSC Part Name="1x2P 3.81mm 每排P数:2", Manufacturer=DORABO(地博电气), Operating Temperature=-40℃~+105℃, Voltage Rating (Max)=300V
B2: "Switching Voltage Regulators 3A, 18V Sync Step-Down DCDC", Manufacturer_Name="Monolithic Power Systems (MPS)", Mouser Part Number=946-MP1484ENLFZ
C1: library part CC1206FKNPO8BN103, JLCPCB Part Class="Extended Part", LCSC Part Name="10nF ±1% 25V", Manufacturer=YAGEO(国巨), Tolerance=±1%
C2 C4 C5 C10 C11: library part RVT1E100M0405, Equivalent Series Resistance(ESR)=-, JLCPCB Part Class="Extended Part", LCSC Part Name="10uF ±20% 25V", Manufacturer=HONOR(荣誉), Operating Temperature=-55℃~+105℃, Tolerance=±20%, Voltage Rating=25V
C3: library part GVZ2A476M1010CNVC, Equivalent Series Resistance(ESR)=700mΩ@100kHz, JLCPCB Part Class="Extended Part", LCSC Part Name="47uF ±20% 100V", Manufacturer=HRK(鸿瑞凯电子), Operating Temperature=-55℃~+105℃, Ripple Current=200mA@100kHz, Tolerance=±20%, Voltage Rating=100V
C6: library part 1206B104K500NT, JLCPCB Part Class="Extended Part", LCSC Part Name="4.7uf ±10% 50V", Manufacturer=FH(风华), Tolerance=±10%
C7 C13 C14 C15 C16 C17 C18 C19 C20 C21 C22 C23 C26 C27 C28 C29 C32 C33 C35 C36: library part 1206B104K500NT, JLCPCB Part Class="Extended Part", LCSC Part Name="100nF ±10% 50V", Manufacturer=FH(风华), Tolerance=±10%
C8: library part CC1206JRNPO9BN682, JLCPCB Part Class="Extended Part", LCSC Part Name="6.8nF ±5% 50V", Manufacturer=YAGEO(国巨), Tolerance=±5%
C9: library part CL31A106KBHNNNE, JLCPCB Part Class="Basic Part", LCSC Part Name="10uF ±10% 50V", Manufacturer=SAMSUNG(三星), Tolerance=±10%
C12 C24 C25: library part 1206B104K500NT, JLCPCB Part Class="Extended Part", Manufacturer=FH(风华), Manufacturer Part=1206X226M250NT1206B104K500NT, Tolerance=±10%
C30 C31: library part RVT10UF25V67RV0020, Equivalent Series Resistance(ESR)=-, JLCPCB Part Class="Extended Part", LCSC Part Name="10uF ±20% 25V", Lifetime @ Temp=2000hrs@105℃, Manufacturer=KNSCHA(科尼盛), Operating Temperature=-55℃~+105℃, Ripple Current=21mA@120Hz, Tolerance=±20%
C34: library part CC1206JKNPOCBN101, JLCPCB Part Class="Extended Part", LCSC Part Name="100pF ±5% 1kV", Manufacturer=YAGEO(国巨), Tolerance=±5%
D1 D2 D5 D6 D7 D8 D9 D10 D11 D12 D13 D14 D15 D16 D22 D23 D25: "2.6 V Red LED SMD", Package=None
D3 D4: library part RS3MB_C2766054, Current - Rectified=3A, JLCPCB Part Class="Extended Part", Manufacturer=WPMtek(维攀), Operating Temperature=-55℃~+150℃@(Tj), Reverse Leakage Current (Ir)=5uA@1000V, Voltage - DC Reverse(Vr)=1kV, Voltage - Forward(Vf@If)=1.3V@3A
D17 D18 D19 D20: Average Rectified Current (Io)=300mA, Forward Voltage (Vf@If)=900mV@100mA, JLCPCB Part Class="Extended Part", LCSC Part Name="电压:40V 电流:300mA", Manufacturer=ST(意法半导体), Reverse Leakage Current (Ir)=1uA@30V, Reverse Voltage (Vr)=40V
D21: library part SS36_C727061, Current - Rectified=3A, JLCPCB Part Class="Extended Part", LCSC Part Name="电压:60V 电流:3A", Manufacturer=TWGMC(台湾迪嘉), Operating Junction Temperature Range=-55℃~+125℃, Reverse Leakage Current (Ir)=500uA, Voltage - DC Reverse(Vr)=60V, Voltage - Forward(Vf@If)=700mV@3A
D24: library part 1N4148W_C917030, Current - Rectified=300mA, JLCPCB Part Class="Extended Part", Manufacturer=JSMSEMI(杰盛微), Non-Repetitive Peak Forward Surge Current=4A, Operating Junction Temperature Range=-55℃~+150℃@(Tj), Pd - Power Dissipation=400mW, Reverse Leakage Current (Ir)=1uA@75V, Voltage - DC Reverse(Vr)=100V, Voltage - Forward(Vf@If)=1.25V@150mA
DIO TACHO: Color=Black, Current Rating (Max)=10A, JLCPCB Part Class="Extended Part", LCSC Part Name="2x4P 3.5mm 排数:2 每排P数:4", Manufacturer=KEFA(科发), Operating Temperature Range=-40℃~+105℃, Soldering Temperature(Max)=-, Voltage Rating (Max)=300V
F1 F2 F3 F4 F5 F6: Current Rating (Max)=100A, Hold Current=2A, JLCPCB Part Class="Extended Part", LCSC Part Name="8V 2A 1812自恢复", Manufacturer=Littelfuse(美国力特), Operating Temperature=-40℃~+85℃, Operating Voltage (Max)=8V, Power Dissipation=-, Resistance - Initial (Ri) (Min)=20mΩ, Resistance - Post Trip (R1) (Max)=70mΩ, Trip Current=3.5A
IC1: "Integrated Circuit", Manufacturer_Name="Espressif Systems"
K10 K12: "5V Trigger Relay Module For Arduino And Raspberry Pi 5V Trigger Relay Module For Arduino And Raspberry Pi", Package="NON STANDARD-5 Songle Relay"
L1: "Inductor"
L2: library part SMMS0630-220M, Current - Saturation(Isat)=3.5A, Current Rating=-, DC Resistance(DCR)=135mΩ, JLCPCB Part Class="Extended Part", LCSC Part Name="22uH ±20% 3.5A", Manufacturer=SXN(顺翔诺), Tolerance=±20%
P1: library part "Header 4", "Header, 4-Pin"
P2: library part "Header 5", "Header, 5-Pin"
P3: Color=White, Current Rating=3A, Flame Retardant Rating=UL94V-0, JLCPCB Part Class="Extended Part", LCSC Part Name="1x2P 间距:2.5mm 直插 系列:XH", Manufacturer=JST, Operating Temperature=-25℃~+85℃, Voltage Rating=250V
P4 P5: "Header, 2-Pin"
PS1: library part AM10CW-4805S-NZ_1, "Power Supply"
Q1 Q2 Q3 Q4 Q5 Q6 Q7 Q8 Q9 Q10 Q11 Q12: library part FMMT493_C686649, Collector Cut-Off Current (Icbo)=100nA, Collector-Emitter Saturation Voltage (VCE(sat)@Ic,Ib)=600mV@1A,100mA, DC Current Gain (hFE@Ic,Vce)=300, JLCPCB Part Class="Extended Part", LCSC Part Name="NPN 电流:1A 耐压:100V", Manufacturer=PJSEMI(平晶微), Operating Temperature=-, Transition Frequency (fT)=150MHz
R1 R2 R5 R6 R13 R14 R24 R25 R26 R29 R32 R33 R34 R45 R46 R47 R48 R49 R60 R61 R62 R63 R64 R72 R73 R74: library part 1206W4J0331T5E, JLCPCB Part Class="Extended Part", LCSC Part Name="330Ω ±5% 250mW 厚膜电阻", Manufacturer=UNI-ROYAL(厚声), Operating Temperature Range=-55℃~+155℃, Temperature Coefficient=±100ppm/℃, Tolerance=±5%
R3 R7 R10 R15 R17 R18 R19 R20 R21 R22 R23 R27 R28 R30 R31 R41 R42 R43 R44 R56 R57 R58 R59 R71 R93 R94 R95 R96 R97 R98 R101 R103 R106 R117: library part 1206W4F1002T5E, JLCPCB Part Class="Basic Part", LCSC Part Name="10kΩ ±1% 250mW 厚膜电阻", Manufacturer=UNI-ROYAL(厚声), Operating Temperature Range=-55℃~+155℃, Temperature Coefficient=±100ppm/℃, Tolerance=±1%
R4 R8 R16 R108 R109 R110 R114: library part 1206W4J0331T5E, JLCPCB Part Class="Extended Part", Manufacturer=UNI-ROYAL(厚声), Manufacturer Part=1206W4J0472T5E, Operating Temperature Range=-55℃~+155℃, Temperature Coefficient=±100ppm/℃, Tolerance=±5%
R9 R85 R86 R88 R92: library part 1206W4F1003T5E, JLCPCB Part Class="Basic Part", LCSC Part Name="100kΩ ±1% 250mW 厚膜电阻", Manufacturer=UNI-ROYAL(厚声), Operating Temperature Range=-55℃~+155℃, Temperature Coefficient=±100ppm/℃, Tolerance=±1%
R11: library part 1206W4F1003T5E, JLCPCB Part Class="Basic Part", Manufacturer=UNI-ROYAL(厚声), Operating Temperature Range=-55℃~+155℃, Temperature Coefficient=±100ppm/℃, Tolerance=±1%
R12: library part 1206W4F1003T5E, JLCPCB Part Class="Basic Part", LCSC Part Name="26.1kΩ ±1% 250mW 厚膜电阻", Manufacturer=UNI-ROYAL(厚声), Operating Temperature Range=-55℃~+155℃, Temperature Coefficient=±100ppm/℃, Tolerance=±1%
R35 R36 R37 R38 R39 R40 R50 R51 R52 R53 R54 R55 R65 R66 R67 R68 R69 R70 R75 R76 R77 R78 R79 R80 R115 R116: library part 1206W4F1001T5E_C4410, JLCPCB Part Class="Basic Part", LCSC Part Name="1kΩ ±1% 250mW 厚膜电阻", Manufacturer=UNI-ROYAL(厚声), Manufacturer Part=1206W4F1001T5E, Operating Temperature Range=-55℃~+155℃, Tolerance=±1%
R81 R82 R87 R89: JLCPCB Part Class="Extended Part", Manufacturer=FOJAN(富捷), Manufacturer Part="FRC1206J473 TS"
R83 R84 R90 R91 R102 R105: library part FRC1206J471TS, JLCPCB Part Class="Extended Part", LCSC Part Name="470Ω ±5% 250mW 厚膜电阻", Manufacturer=FOJAN(富捷), Operating Temperature=-55℃~+155℃, Power(Watts)=250mW, Temperature Coefficient=±100ppm/℃, Tolerance=±5%, Voltage-Supply(Max)=200V
R99: library part FRC1206F6202TS, JLCPCB Part Class="Extended Part", LCSC Part Name="62kΩ ±1% 250mW 厚膜电阻", Manufacturer=FOJAN(富捷), Operating Temperature=-55℃~+155℃, Power(Watts)=250mW, Temperature Coefficient=±100ppm/℃, Tolerance=±1%, Voltage-Supply(Max)=200V
R100: library part FRC1206F3301TS, JLCPCB Part Class="Extended Part", LCSC Part Name="3.3kΩ ±1% 250mW 厚膜电阻", Manufacturer=FOJAN(富捷), Operating Temperature=-55℃~+155℃, Power(Watts)=250mW, Temperature Coefficient=±100ppm/℃, Tolerance=±1%, Voltage-Supply(Max)=200V
R104: library part FRC1206F2002TS, JLCPCB Part Class="Extended Part", LCSC Part Name="20kΩ ±1% 250mW 厚膜电阻", Manufacturer=FOJAN(富捷), Operating Temperature=-55℃~+155℃, Power(Watts)=250mW, Temperature Coefficient=±100ppm/℃, Tolerance=±1%, Voltage-Supply(Max)=200V
R107 R111: library part FRC1206F2401TS, JLCPCB Part Class="Extended Part", LCSC Part Name="2.4kΩ ±1% 250mW 厚膜电阻", Manufacturer=FOJAN(富捷), Operating Temperature=-55℃~+155℃, Power(Watts)=250mW, Temperature Coefficient=±100ppm/℃, Tolerance=±1%, Voltage-Supply(Max)=200V
R112: library part 1206W4F1200T5E_C17909, JLCPCB Part Class="Basic Part", LCSC Part Name="120Ω ±1% 250mW 厚膜电阻", Manufacturer=UNI-ROYAL(厚声), Manufacturer Part=1206W4F1200T5E, Operating Temperature Range=-55℃~+155℃, Temperature Coefficient=±100ppm/℃, Tolerance=±1%
R113: library part RC1206FR-0756KL, JLCPCB Part Class="Extended Part", LCSC Part Name="厚膜电阻 56kΩ ±1% 250mW", Manufacturer=YAGEO(国巨), Operating Temperature Range=-55℃~+155℃, Power(Watts)=250mW, Temperature Coefficient=±100ppm/℃, Tolerance=±1%
RELAY RELAY2: Color=Black, Current Rating (Max)=10A, JLCPCB Part Class="Extended Part", LCSC Part Name="2x9P 3.5mm 排数:2 每排P数:9", Manufacturer=KEFA(科发), Operating Temperature Range=-40℃~+105℃, Soldering Temperature(Max)=-, Voltage Rating (Max)=300V
RS1: Color=Black, Current Rating (Max)=10A, JLCPCB Part Class="Extended Part", LCSC Part Name="2x2P 3.5mm 排数:2 每排P数:2", Manufacturer=KEFA(科发), Operating Temperature Range=-40℃~+105℃, Soldering Temperature(Max)=-, Voltage Rating (Max)=300V
SW1: Actuator/Cap Color=Black, Contact Current=50mA, Insulation Resistance=100MΩ, JLCPCB Part Class="Basic Part", LCSC Part Name="4*3*2mm 立贴 轻触开关", Manufacturer=XUNPU(讯普), Operating Force=160gf, Operating Temperature=-30℃~+80℃, Voltage Rating (DC)=12V
TEMP: Color=Black, Current Rating=10A, JLCPCB Part Class="Extended Part", LCSC Part Name="2x3P 3.5mm 排数:2 每排P数:3", Manufacturer=KEFA(科发), Operating Temperature=-40℃~+105℃, Voltage Rating (Max)=300V
U1 U7 U35: library part B0505S-1WR3_C7465178, input voltage (Vdc)=4.5V~5.5V, Insulated Voltage=1.5kV, JLCPCB Part Class="Extended Part", LCSC Part Name="DC-DC输入5V输出5V200mA 1W输出短路保护", Manufacturer=EVISUN(易成), Maximum Capacitive Load=2400uF, Output Current (Max)=200mA, Output Voltage=5V, Power=1W
U2 U3 U5 U6 U9 U10 U11 U12 U13 U14 U15 U16 U17 U18 U19 U20 U21 U22 U23 U24 U25 U26 U27 U28: library part PC817C_C302516, Collector-Emitter Saturation Voltage (Vce(sat)@Ic,IF)=200mV@1mA,20mA, Forward Voltage=1.4V, Input voltage type=DC, Isolation Voltage(rms)=5kV, JLCPCB Part Class="Extended Part", LCSC Part Name=光耦-光电晶体管输出, Manufacturer=AOTE(奥特), Operating Temperature=-55℃~+100℃, Output Current=50mA, Reverse Voltage=6V
U4: Frequency - Switching=1.2MHz, JLCPCB Part Class="Extended Part", LCSC Part Name="老版本 高效1.2MHz 2A升压转换器", Manufacturer=西安航天民芯, Operating Temperature=-40℃~+85℃, Output Current=2A, Output Voltage=-, Quiescent Current=100uA；1.6mA, Voltage - Supply=2V~24V
U8: "Remote 8-bit I/O expander for I2C-bus", Package=None
U29 U30 U31 U32: library part LM321_C880719, JLCPCB Part Class="Extended Part", Manufacturer=Slkor(萨科微)
U33 U34: JLCPCB Part Class="Extended Part", LCSC Part Name="DC输入 1通道", Manufacturer=LITEON(光宝), Operating Temperature=-40℃~+85℃, Supply Voltage=4.5V~5.5V
U36: library part SN75176BDR_C7063, JLCPCB Part Class="Extended Part", LCSC Part Name="5V供电 收发器", Manufacturer=TI(德州仪器), Operating Temperature=0℃~+70℃, Supply Voltage=4.75V~5.25V
U37 U38 U40: Breakdown Voltage=6V, JLCPCB Part Class="Extended Part", Manufacturer=LANKE(兰科), Maximum Clamping Voltage=12V@Typ, Peak Pulse Current (Ipp)@10/1000us=40A@8/20us, Peak Pulse Power Dissipation (Ppp)@10/1000us=480W, Reverse Leakage Current (Ir)=500nA, Reverse Stand-Off Voltage (Vrwm)=5V@Max
U39: library part CD4069_C3041279, JLCPCB Part Class="Extended Part", Manufacturer=Slkor(萨科微), Supply Current (Max)=1uA, Supply Voltage(Single)=3V~15V
U41 U43: Color=Black, Current Rating=17.5A, JLCPCB Part Class="Extended Part", LCSC Part Name="7.62mm 1x2P 每排P数:2 排数:1 弯针", Manufacturer=DORABO(地博电气), Operating Temperature=-40℃~+105℃, Voltage Rating (Max)=450V
U42 U44: JLCPCB Part Class="Extended Part", LCSC Part Name=MAX6675ISA, Manufacturer=ADI(亚德诺)/MAXIM(美信), Operating Temperature=-20℃~+85℃, Voltage - Supply=3V~5.5V
VIB: Color=Black, Current Rating (Max)=10A, JLCPCB Part Class="Extended Part", LCSC Part Name="2x6P 3.5mm 排数:2 每排P数:6", Manufacturer=KEFA(科发), Operating Temperature Range=-40℃~+105℃, Soldering Temperature(Max)=-, Voltage Rating (Max)=300V

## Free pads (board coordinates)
  round 4.5 hole 3.2: MTH1(944.753,210.439) MTH1(945.388,123.317) MTH1(1137.666,171.831) MTH1(1226.058,123.317) MTH1(1226.693,210.439)

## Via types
v1: diameter 0.6, hole 0.3, Top Layer to Bottom Layer, 154 vias
v2: diameter 1.27, hole 0.711, Top Layer to Bottom Layer, 80 vias
v3: diameter 2.4, hole 1.6, Top Layer to Bottom Layer, 4 vias
v4: diameter 1.5, hole 1, Top Layer to Bottom Layer, 2 vias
